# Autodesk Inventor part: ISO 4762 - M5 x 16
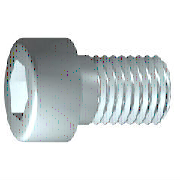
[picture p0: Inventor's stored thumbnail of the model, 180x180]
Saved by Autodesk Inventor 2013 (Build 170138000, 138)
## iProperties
Created: 2012-02
Part Number: ISO 4762 - M5 x 16
Material: Edelstahl, 440C
Description: Innensechskantschraube
Document SubType Name: Modeling
Standard: ISO 4762
Designer: Dan
Standard Revision: 1998
Standards Organization: DIN
Language: de-DE
Size Designation: M5 x 16
Categories: <MemberInstance><Categories><Category DisplayName="Verbindungselemente" InternalName="e4da775c-781d-43d5-af7c-5136215cf5a6" Mnemonic="FSTN"><Category DisplayNam
Density: 7.75 g/cm^3
IsCustomPart: 0
Author: Dan
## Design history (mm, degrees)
sketch "Skizze1"
  geometry: L1 (-1.167, 0)-(16, 0); L2 (16, 0)-(16, 2.5); L3 (16, 2.5)-(2, 2.5); L4 (2, 2.5)-(1.509, 2.5); L5 (1.509, 2.5)-(0, 2.5); L6 (0, 2.5)-(0, 4.25); L7 (0, 4.25)-(-5, 4.25); L8 (-5, 4.25)-(-5, 2.309); L9 (-5, 2.309)-(-2.5, 2.309); L10 (-2.5, 2.309)-(-1.167, 0); L11 (-9.2, 0)-(20.2, 0) reference; L12 (0, -0.85)-(0, 5.1) reference; L13 (2, 2.5)-(0, 2.5)
  constraints: 22 end point, 6 parallel, 2 collinear, 2 perpendicular, 1 horizontal, 1 point on line
  dimensions: "d1" = 14 distance from line of L3.end L2 (= GEL); "d2" = 0.49086 distance of L4.end L3.end (computed from GAL); "d3" = 5 distance between parallel lines of L8 L6 (= KOH); "d4" = 2.5 distance of L8.end L9.end (= INTI); "d5" = 60 deg angle of L10 L1; "d6" = 5 diameter of L3 L1 (= GD); "d7" = 5 diameter of L5 L1 (= BDM); "d8" = 4.6188 diameter of L9 L1 (= 1.1547 x SW); "d9" = 8.5 diameter of L7 L1 (= KOD); "d26" = 16 distance between parallel lines of L12 L2 (= NLG)
revolve "Körper" sketch "Skizze1" stored, may be unused: angle "d10" = 90 deg
sketch "Skizze2"
  geometry: L1 (0, -5.95)-(0, 5.95) reference; L2 (-5.95, 0)-(5.95, 0) reference; L3 (2.309, 0)-(1.155, -2); L4 (1.155, -2)-(-1.155, -2); L5 (-1.155, -2)-(-2.309, 0); L6 (-2.309, 0)-(-1.155, 2); L7 (-1.155, 2)-(1.155, 2); L8 (1.155, 2)-(2.309, 0); 2 further points
  constraints: 12 end point, 1 coincident, 1 horizontal alignment, 1 point on line, 12 other
extrude "Loch" join sketch "Skizze2" stored distance "d11" = 10; taper "d12" = 0 deg
workplane "Work Plane1"
fillet "Fillet2" dims "d30" = 0.1 (= R)
body "Solid1"
fillet "Rundung1" dims "d17" = 0.5 (= RR)
feature "Gewinde" dims "d13" = 14 (= GEL), "d14" = 0
chamfer "Fase1" distance "d15" = 0.49076 (= -0.5 x SPD + 0.5 x GD); stored, may be unused: second distance "d16" = 0.49076 (= GUL), angle "d27" = 45 deg
other parameters: "GD" = 5 [user parameter; used in 2 equation terms], "NLG" = 16 [user parameter; used in 1 equation term], "GEL" = 14 [user parameter; used in 2 equation terms], "KOD" = 8.5 [user parameter; used in 1 equation term], "KOH" = 5 [user parameter; used in 1 equation term], "INTI" = 2.5 [user parameter; used in 1 equation term], "GAL" = 0.49076 (= 0.61345 x PTC) [user parameter; used in 1 equation term], "GUL" = 0.49076 (= 0.61345 x PTC) [user parameter; used in 1 equation term], "BDM" = 5 (= NND) [user parameter; used in 1 equation term], "SW" = 4 [user parameter; used in 2 equation terms], "RR" = 0.5 [user parameter; used in 1 equation term], "SPD" = 4.01848 (= NND - 1.2269 x PTC) [user parameter; used in 1 equation term], "d19" = 0, "d28" = 0, "d29" = 0, "R" = 0.1 [user parameter; used in 1 equation term], "TOA" = 30 deg [user parameter], "GD1" = 4.01848 (= THREADDIA - 1.2269 x PTC) [user parameter], "THREADDIA" = 5 [user parameter; used in 1 equation term], "FAWI" = 45 deg [user parameter], "TPU" = 12.5 (computed from PTC) [user parameter], "PTC" = 0.8 [user parameter; used in 5 equation terms], "NND" = 5 [user parameter; used in 2 equation terms], "E0" = 4.62 (= 1.155 x SW) [user parameter]
